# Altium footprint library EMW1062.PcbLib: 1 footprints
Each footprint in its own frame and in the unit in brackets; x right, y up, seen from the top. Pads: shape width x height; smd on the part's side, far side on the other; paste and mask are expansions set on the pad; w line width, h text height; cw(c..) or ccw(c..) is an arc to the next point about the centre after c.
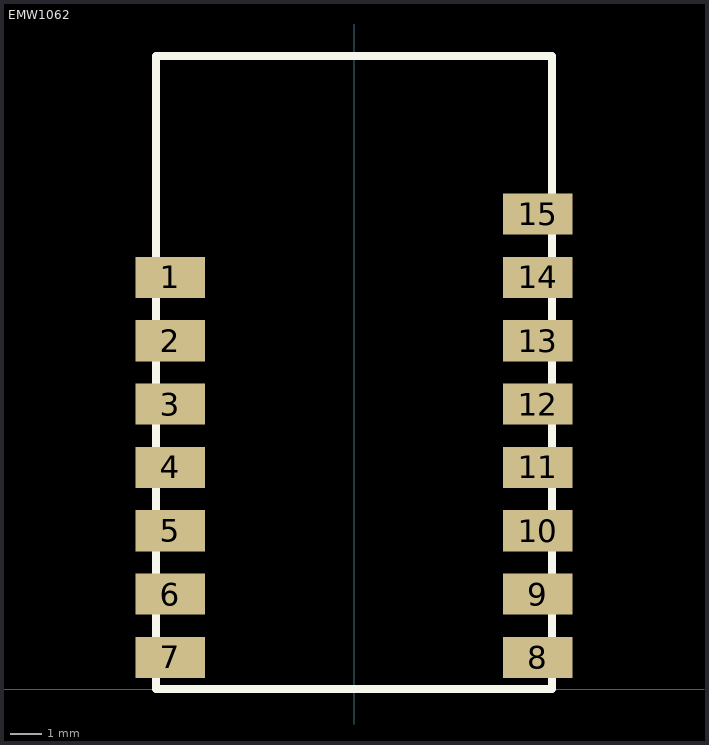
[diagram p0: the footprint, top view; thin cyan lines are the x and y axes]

## EMW1062 [mm]
pads (15):
  rect 2.2x1.3 smd: 1(-5.8,13) 2(-5.8,11) 3(-5.8,9) 4(-5.8,7) 5(-5.8,5) 6(-5.8,3) 7(-5.8,1) 8(5.8,1) 9(5.8,3) 10(5.8,5) 11(5.8,7) 12(5.8,9) 13(5.8,11) 14(5.8,13) 15(5.8,15)
Top Overlay:
  lines w0.254: -6.25,0 6.25,0 6.25,20 -6.25,20 -6.25,0
3D body: height 2.05, standoff 1, extent -6.05,17.75 3.45,19.85
3D body: height 1, standoff 0, extent -6.257,4.35 -5.257,5.65
3D body: height 1, standoff 0, extent -6.267,2.35 -5.267,3.65
3D body: height 1, standoff 0, extent -6.252,0.35 -5.252,1.65
3D body: height 1, standoff 0, extent 5.255,0.35 6.255,1.65
3D body: height 1, standoff 0, extent 5.255,2.35 6.255,3.65
3D body: height 1, standoff 0, extent 5.255,6.35 6.255,7.65
3D body: height 1, standoff 0, extent 5.255,4.35 6.255,5.65
3D body: height 1, standoff 0, extent 5.255,8.35 6.255,9.65
3D body: height 1, standoff 0, extent 5.255,10.35 6.255,11.65
3D body: height 1, standoff 0, extent 5.255,14.35 6.255,15.65
3D body: height 1, standoff 0, extent 5.255,12.35 6.255,13.65
3D body: height 1, standoff 0, extent -6.252,8.35 -5.252,9.65
3D body: height 1, standoff 0, extent -6.262,6.35 -5.262,7.65
3D body: height 1, standoff 0, extent -6.267,10.35 -5.267,11.65
3D body: height 1, standoff 0, extent -6.257,12.35 -5.257,13.65
3D body: height 2.45, standoff 1.19, extent 1.8,14.35 4.8,17.45
3D body: height 2.6, standoff 1, extent -4.9,0.05 4.9,15
3D body: height 1, standoff 0, extent -6.265,10.45 -5.774,11.45
3D body: height 1, standoff 0, extent -6.265,6.5 -5.774,7.5
3D body: height 1, standoff 0, extent -6.265,8.5 -5.774,9.5
3D body: height 1, standoff 0, extent -6.265,12.5 -5.774,13.5
3D body: height 1, standoff 0, extent -6.265,4.5 -5.774,5.5
3D body: height 1, standoff 0, extent -6.265,2.5 -5.774,3.5
3D body: height 1, standoff 0, extent -6.265,0.5 -5.774,1.5
3D body: height 1, standoff 0, extent 5.765,0.5 6.256,1.5
3D body: height 1, standoff 0, extent 5.765,2.5 6.256,3.5
3D body: height 1, standoff 0, extent 5.765,4.5 6.256,5.5
3D body: height 1, standoff 0, extent 5.765,6.5 6.256,7.5
3D body: height 1, standoff 0, extent 5.765,8.5 6.256,9.5
3D body: height 1, standoff 0, extent 5.765,10.5 6.256,11.5
3D body: height 1, standoff 0, extent 5.765,12.5 6.256,13.5
3D body: height 1, standoff 0, extent 5.765,14.5 6.256,15.5
3D body: height 1, standoff 0, extent -6.25,0 6.25,20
